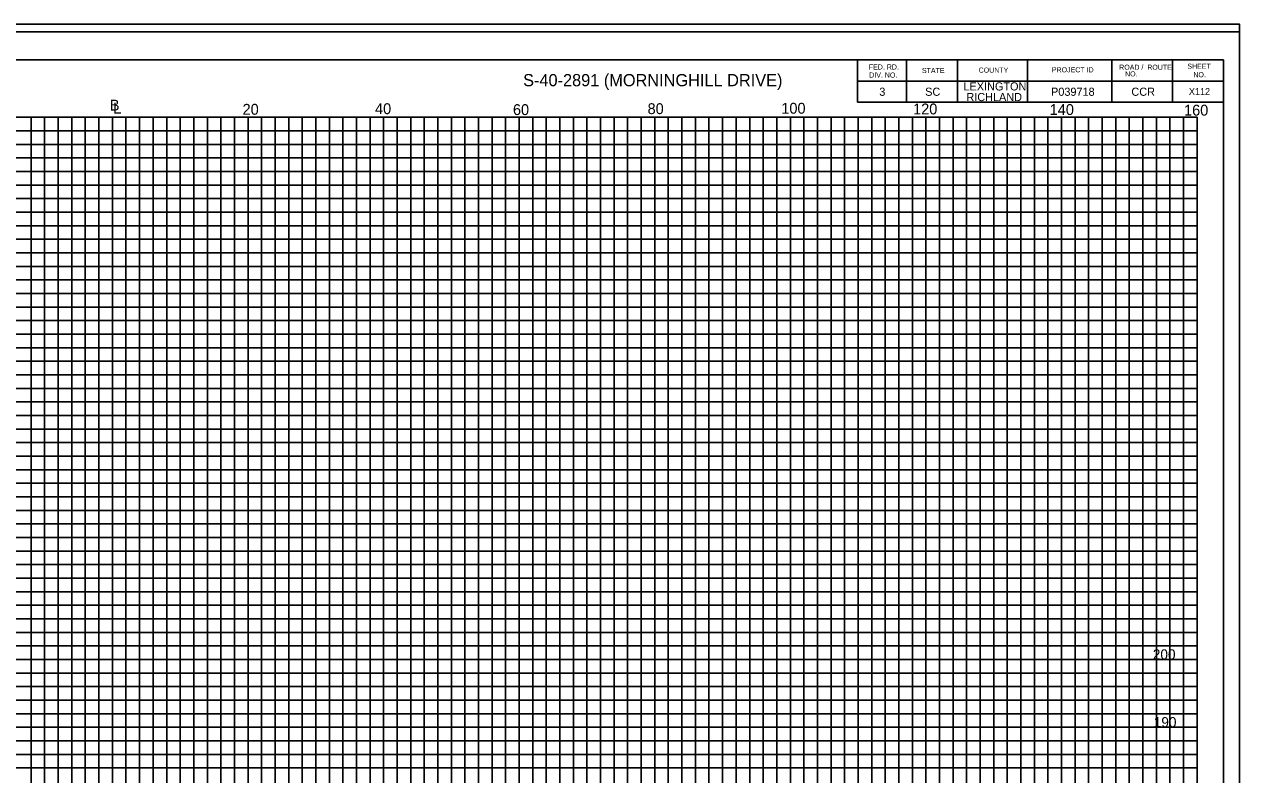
# Model space of a CAD drawing. Extents: x 967 to 1326, y 964 to 2584.
# Drawn here: x 1147 to 1326.3, y 2473 to 2583.7 of the extents above; entities that cross this region are included whole.
import ezdxf

# ---------------------------------------------------------------- set-up
doc = ezdxf.new("R2010")
doc.units = 0
for name, color, linetype in [('Default', 7, 'Continuous'), ('RD_GPK_XS_Cell', 7, 'Continuous'), ('RD_XS_ExGround', 7, 'Continuous'), ('RD_XS_ExPaveRet', 7, 'Continuous'), ('RD_XS_Misc_Line', 7, 'Continuous'), ('RD_XS_TX_Elev_EX', 7, 'Continuous')]:
    doc.layers.add(name, color=color, linetype=linetype)

msp = doc.modelspace()

# ---------------------------------------------------------------- linework, layer by layer
at = {"layer": 'RD_GPK_XS_Cell'}
for p, q in [((1000, 2570), (1320, 2570)), ((1150, 2400), (1150, 2570)), ((1160, 2400), (1160, 2570)), ((1170, 2400), (1170, 2570)), ((1180, 2400), (1180, 2570)), ((1190, 2400), (1190, 2570)), ((1200, 2400), (1200, 2570)), ((1210, 2400), (1210, 2570)), ((1220, 2400), (1220, 2570)), ((1230, 2400), (1230, 2570)), ((1240, 2400), (1240, 2570)), ((1250, 2400), (1250, 2570)), ((1260, 2400), (1260, 2570)), ((1270, 2400), (1270, 2570)), ((1280, 2400), (1280, 2570)), ((1290, 2400), (1290, 2570)), ((1300, 2400), (1300, 2570)), ((1310, 2400), (1310, 2570)), ((1320, 2400), (1320, 2570)), ((1000, 2560), (1320, 2560)), ((1000, 2550), (1320, 2550)), ((1000, 2540), (1320, 2540)), ((1000, 2530), (1320, 2530)), ((1000, 2520), (1320, 2520)), ((1000, 2510), (1320, 2510)), ((1000, 2500), (1320, 2500)), ((1000, 2490), (1320, 2490)), ((1000, 2480), (1320, 2480))]:
    msp.add_line(p, q, dxfattribs=at)
at = {"layer": 'RD_XS_ExGround'}
for p, q in [((1148, 2400), (1148, 2570)), ((1152, 2400), (1152, 2570)), ((1154, 2400), (1154, 2570)), ((1156, 2400), (1156, 2570)), ((1158, 2400), (1158, 2570)), ((1162, 2400), (1162, 2570)), ((1164, 2400), (1164, 2570)), ((1166, 2400), (1166, 2570)), ((1168, 2400), (1168, 2570)), ((1172, 2400), (1172, 2570)), ((1174, 2400), (1174, 2570)), ((1176, 2400), (1176, 2570)), ((1178, 2400), (1178, 2570)), ((1182, 2400), (1182, 2570)), ((1184, 2400), (1184, 2570)), ((1186, 2400), (1186, 2570)), ((1188, 2400), (1188, 2570)), ((1192, 2400), (1192, 2570)), ((1194, 2400), (1194, 2570)), ((1196, 2400), (1196, 2570)), ((1198, 2400), (1198, 2570)), ((1202, 2400), (1202, 2570)), ((1204, 2400), (1204, 2570)), ((1206, 2400), (1206, 2570)), ((1208, 2400), (1208, 2570)), ((1212, 2400), (1212, 2570)), ((1214, 2400), (1214, 2570)), ((1216, 2400), (1216, 2570)), ((1218, 2400), (1218, 2570)), ((1222, 2400), (1222, 2570)), ((1224, 2400), (1224, 2570)), ((1226, 2400), (1226, 2570)), ((1228, 2400), (1228, 2570)), ((1232, 2400), (1232, 2570)), ((1234, 2400), (1234, 2570)), ((1236, 2400), (1236, 2570)), ((1238, 2400), (1238, 2570)), ((1242, 2400), (1242, 2570)), ((1244, 2400), (1244, 2570)), ((1246, 2400), (1246, 2570)), ((1248, 2400), (1248, 2570)), ((1252, 2400), (1252, 2570)), ((1254, 2400), (1254, 2570)), ((1256, 2400), (1256, 2570)), ((1258, 2400), (1258, 2570)), ((1262, 2400), (1262, 2570)), ((1264, 2400), (1264, 2570)), ((1266, 2400), (1266, 2570)), ((1268, 2400), (1268, 2570)), ((1272, 2400), (1272, 2570)), ((1274, 2400), (1274, 2570)), ((1276, 2400), (1276, 2570)), ((1278, 2400), (1278, 2570)), ((1282, 2400), (1282, 2570)), ((1284, 2400), (1284, 2570)), ((1286, 2400), (1286, 2570)), ((1288, 2400), (1288, 2570)), ((1292, 2400), (1292, 2570)), ((1294, 2400), (1294, 2570)), ((1296, 2400), (1296, 2570)), ((1298, 2400), (1298, 2570)), ((1302, 2400), (1302, 2570)), ((1304, 2400), (1304, 2570)), ((1306, 2400), (1306, 2570)), ((1308, 2400), (1308, 2570)), ((1312, 2400), (1312, 2570)), ((1314, 2400), (1314, 2570)), ((1316, 2400), (1316, 2570)), ((1318, 2400), (1318, 2570)), ((1000, 2568), (1320, 2568)), ((1000, 2566), (1320, 2566)), ((1000, 2564), (1320, 2564)), ((1000, 2562), (1320, 2562)), ((1000, 2558), (1320, 2558)), ((1000, 2556), (1320, 2556)), ((1000, 2554), (1320, 2554)), ((1000, 2552), (1320, 2552)), ((1000, 2548), (1320, 2548)), ((1000, 2546), (1320, 2546)), ((1000, 2544), (1320, 2544)), ((1000, 2542), (1320, 2542)), ((1000, 2538), (1320, 2538)), ((1000, 2536), (1320, 2536)), ((1000, 2534), (1320, 2534)), ((1000, 2532), (1320, 2532)), ((1000, 2528), (1320, 2528)), ((1000, 2526), (1320, 2526)), ((1000, 2524), (1320, 2524)), ((1000, 2522), (1320, 2522)), ((1000, 2518), (1320, 2518)), ((1000, 2516), (1320, 2516)), ((1000, 2514), (1320, 2514)), ((1000, 2512), (1320, 2512)), ((1000, 2508), (1320, 2508)), ((1000, 2506), (1320, 2506)), ((1000, 2504), (1320, 2504)), ((1000, 2502), (1320, 2502)), ((1000, 2498), (1320, 2498)), ((1000, 2496), (1320, 2496)), ((1000, 2494), (1320, 2494)), ((1000, 2492), (1320, 2492)), ((1000, 2488), (1320, 2488)), ((1000, 2486), (1320, 2486)), ((1000, 2484), (1320, 2484)), ((1000, 2482), (1320, 2482)), ((1000, 2478), (1320, 2478)), ((1000, 2476), (1320, 2476)), ((1000, 2474), (1320, 2474))]:
    msp.add_line(p, q, dxfattribs=at)
at = {"layer": 'RD_XS_ExPaveRet'}
for points in [[(967.41, 2363.72), (1326.28, 2363.72), (1326.28, 2583.72), (967.41, 2583.72)], [(988.52, 2364.84), (1326.28, 2364.84), (1326.28, 2582.6), (988.52, 2582.6)]]:
    msp.add_lwpolyline(points, close=True, dxfattribs=at)
at = {"layer": 'RD_XS_TX_Elev_EX'}
for p, q in [((996.11, 2578.46), (1323.89, 2578.46)), ((1269.89, 2578.46), (1269.89, 2572.21)), ((1277.14, 2578.46), (1277.14, 2572.21)), ((1284.64, 2578.46), (1284.64, 2572.21)), ((1295, 2578.46), (1295, 2572.21)), ((1307.43, 2578.46), (1307.43, 2572.21)), ((1316.39, 2578.46), (1316.39, 2572.21)), ((1323.89, 2578.46), (1323.89, 2368.98)), ((1269.89, 2575.33), (1323.89, 2575.33)), ((1269.89, 2572.21), (1323.89, 2572.21))]:
    msp.add_line(p, q, dxfattribs=at)

# ---------------------------------------------------------------- texts
at = {"layer": 'Default'}
for s, height, p in [('X112', 1, (1318.79, 2573.3)), ('200', 1.5, (1313.47, 2490)), ('190', 1.5, (1313.61, 2480))]:
    msp.add_text(s, height=height, dxfattribs=at).set_placement(p)
at = {"layer": 'RD_XS_Misc_Line'}
msp.add_text('S-40-2891 (MORNINGHILL DRIVE)', height=1.8, rotation=0, dxfattribs=at).set_placement((1220.58, 2574.58))
for s, height, p in [('FED. RD.', 0.75, (1271.58, 2577.05)), ('DIV. NO.', 0.75, (1271.64, 2575.86)), ('STATE', 0.75, (1279.41, 2576.53)), ('COUNTY', 0.75, (1287.78, 2576.59)), ('PROJECT ID', 0.75, (1298.58, 2576.63)), ('ROAD /  ROUTE', 0.75, (1308.51, 2577.01)), ('   NO.', 0.75, (1308.51, 2576.03)), ('SHEET', 0.75, (1318.56, 2577.16)), ('NO.', 0.75, (1319.45, 2575.91)), ('LEXINGTON', 1.2, (1285.54, 2573.96)), ('3', 1.2, (1273.12, 2573.17)), ('SC', 1.2, (1279.89, 2573.17)), ('RICHLAND', 1.2, (1285.97, 2572.39)), ('P039718', 1.2, (1298.46, 2573.17)), ('CCR', 1.2, (1310.31, 2573.17)), ('B', 1.6, (1159.61, 2570.99)), ('L', 1.6, (1160.12, 2570.54)), ('20', 1.6, (1179.2, 2570.38)), ('40', 1.6, (1198.74, 2570.47)), ('60', 1.6, (1219.08, 2570.33)), ('80', 1.6, (1238.94, 2570.47)), ('100', 1.6, (1258.67, 2570.53)), ('120', 1.6, (1278.11, 2570.43)), ('140', 1.6, (1298.26, 2570.34)), ('160', 1.6, (1318.08, 2570.25))]:
    msp.add_text(s, height=height, dxfattribs=at).set_placement(p)

doc.saveas('drawing.dxf')
